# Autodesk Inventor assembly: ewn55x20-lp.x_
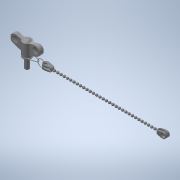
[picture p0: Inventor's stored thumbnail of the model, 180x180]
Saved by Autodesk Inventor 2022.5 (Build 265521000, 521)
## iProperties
Created: 2021-08
Part Number: ewn55x20-lp.x_
Material: 一般
Document SubType Name: Assembly
Designer: ImaoCorp
Sending System: SOLIDWORKS 2019-2019304
MC: AMD64
MC_MODEL: Intel64 Family 6 Model 60 Stepping 3, GenuineIntel
OS: Windows_NT
FRU: Parasolid Version 31.0, build 290,  9- 1-2019
FORMAT: text
GUISE: transmit
KEY: ewn55x20-lp
FILE: ewn55x20-lp.x_t
DATE: Wed Aug 11 15:05:49 2021
Author: ImaoCorp
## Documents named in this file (3)
- X:\14_SW2022-Inv2022\00_全2023-1023新製品(TCC)まで\e\ewn55x20-lp\EWN55X20-LP.iam
- X:\14_SW2022-Inv2022\00_全2023-1023新製品(TCC)まで\e\ewn55x20-lp\ewn55x20-lp_01.ipt
- X:\14_SW2022-Inv2022\00_全2023-1023新製品(TCC)まで\e\ewn55x20-lp\ewn55x20-lp_02.ipt
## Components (2 placed, 2 different names)
1. ewn55x20-lp_01
2. ewn55x20-lp_02
